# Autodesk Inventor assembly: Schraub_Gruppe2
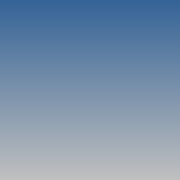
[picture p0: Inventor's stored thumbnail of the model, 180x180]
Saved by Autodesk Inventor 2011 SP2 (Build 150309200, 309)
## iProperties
Created: 2012-06
Part Number: Schraub_Gruppe2
Document SubType Name: Assembly
Designer: JRE
Author: JRE
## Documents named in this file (4)
- E:\Users\jre\Documents\Inventor\Test\Schraub_Gruppe2.iam
- C:\Users\JRE\Documents\Inventor\Content Center Files\R2011\de-DE\DIN 125-1  A\DIN 125 - A 17.ipt
- C:\Users\JRE\Documents\Inventor\Content Center Files\R2011\de-DE\DIN 127 - W\DIN 127 - A 16.ipt
- C:\Users\JRE\Documents\Inventor\Content Center Files\R2011\de-DE\DIN 934\DIN 934 - M16 x 2.ipt
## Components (3 placed, 3 different names)
1. DIN 125-1 A A 17:1
2. DIN 127 - zurückgezogen A 16:1
3. DIN 934 - ersetzt durch DIN EN 24032/28673/28674 M16:1
## Named parameters: d5_d0 = 0
